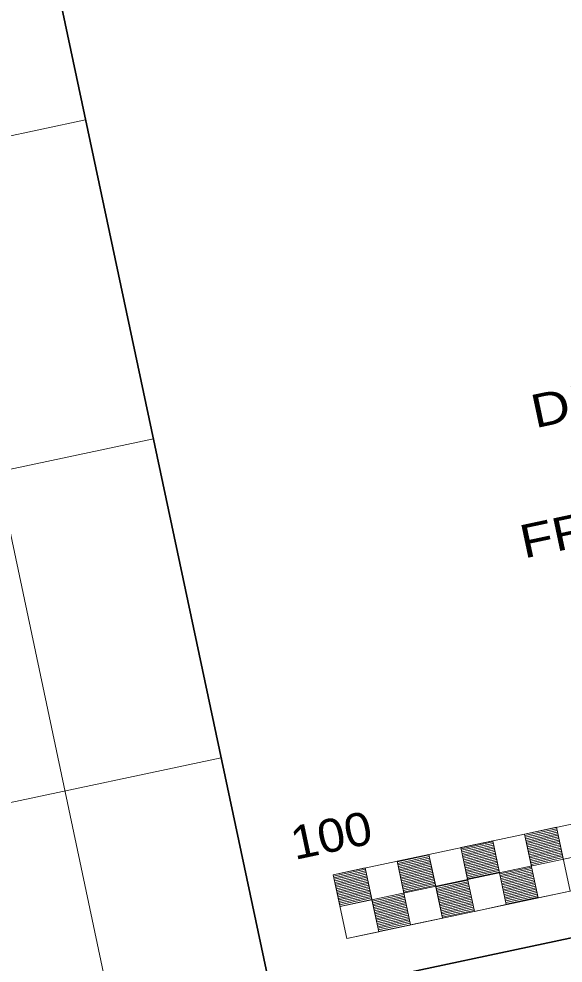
# Model space of a CAD drawing. Extents: x 2357218 to 2371708, y 6973728 to 6980157.
# Drawn here: x 2370463.2 to 2370630.2, y 6976807.8 to 6977097.4 of the extents above; entities that cross this region are included whole.
import ezdxf
from ezdxf.enums import TextEntityAlignment as Align

# ---------------------------------------------------------------- set-up
doc = ezdxf.new("R2010")
doc.units = 0
doc.header["$LTSCALE"] = 2
doc.layers.add('62', color=7, linetype='Continuous', lineweight=13)
doc.layers.add('63', color=7, linetype='Continuous', lineweight=13)

msp = doc.modelspace()

# ---------------------------------------------------------------- linework, layer by layer
at = {"layer": '62'}
for p, q in [((2370248.639, 6977936.603), (2370539.727, 6976567.134)), ((2370483.709, 6977066.421), (2358649.527, 6974550.988)), ((2370504.501, 6976968.6), (2358670.319, 6974453.169)), ((2370559.68, 6976834.897), (2370950.993, 6976918.073)), ((2370561.761, 6976825.114), (2370953.073, 6976908.29)), ((2370525.293, 6976870.783), (2358691.111, 6974355.349)), ((2370618.379, 6976847.361), (2370628.163, 6976849.442)), ((2370618.483, 6976846.872), (2370628.267, 6976848.952)), ((2370628.16, 6976849.453), (2370630.24, 6976839.67)), ((2370618.377, 6976847.373), (2370620.456, 6976837.591)), ((2370618.587, 6976846.381), (2370628.37, 6976848.462)), ((2370618.692, 6976845.892), (2370628.474, 6976847.974)), ((2370618.795, 6976845.404), (2370628.578, 6976847.483)), ((2370618.899, 6976844.915), (2370628.683, 6976846.995)), ((2370619.004, 6976844.427), (2370628.786, 6976846.505)), ((2370619.107, 6976843.937), (2370628.89, 6976846.016)), ((2370598.811, 6976843.214), (2370600.89, 6976833.431)), ((2370598.882, 6976842.88), (2370608.665, 6976844.957)), ((2370598.986, 6976842.39), (2370608.769, 6976844.469)), ((2370599.09, 6976841.9), (2370608.873, 6976843.979)), ((2370599.195, 6976841.411), (2370608.977, 6976843.489)), ((2370599.298, 6976840.921), (2370609.081, 6976843.002)), ((2370608.594, 6976845.295), (2370610.673, 6976835.511)), ((2370619.212, 6976843.448), (2370628.995, 6976845.527)), ((2370619.316, 6976842.959), (2370629.098, 6976845.038)), ((2370619.419, 6976842.469), (2370629.203, 6976844.549)), ((2370619.523, 6976841.981), (2370629.307, 6976844.059)), ((2370619.627, 6976841.491), (2370629.41, 6976843.571)), ((2370619.732, 6976841.002), (2370629.514, 6976843.082)), ((2370579.286, 6976838.872), (2370589.069, 6976840.951)), ((2370579.39, 6976838.383), (2370589.172, 6976840.462)), ((2370579.494, 6976837.892), (2370589.277, 6976839.973)), ((2370589.029, 6976841.136), (2370591.109, 6976831.353)), ((2370599.403, 6976840.433), (2370609.186, 6976842.513)), ((2370599.506, 6976839.943), (2370609.29, 6976842.023)), ((2370599.61, 6976839.454), (2370609.394, 6976841.534)), ((2370599.715, 6976838.965), (2370609.498, 6976841.045)), ((2370599.819, 6976838.476), (2370609.601, 6976840.556)), ((2370599.922, 6976837.987), (2370609.706, 6976840.067)), ((2370619.835, 6976840.513), (2370629.618, 6976842.592)), ((2370619.939, 6976840.024), (2370629.723, 6976842.104)), ((2370620.044, 6976839.535), (2370629.826, 6976841.614)), ((2370620.147, 6976839.046), (2370629.93, 6976841.125)), ((2370620.252, 6976838.557), (2370630.034, 6976840.636)), ((2370620.356, 6976838.068), (2370630.137, 6976840.147)), ((2370569.463, 6976836.975), (2370571.543, 6976827.193)), ((2370579.246, 6976839.056), (2370581.325, 6976829.274)), ((2370579.598, 6976837.404), (2370589.38, 6976839.483)), ((2370579.701, 6976836.913), (2370589.484, 6976838.995)), ((2370579.805, 6976836.425), (2370589.588, 6976838.506)), ((2370579.909, 6976835.936), (2370589.693, 6976838.016)), ((2370580.014, 6976835.447), (2370589.797, 6976837.528)), ((2370580.118, 6976834.959), (2370589.9, 6976837.037)), ((2370600.026, 6976837.498), (2370609.809, 6976839.577)), ((2370600.13, 6976837.009), (2370609.914, 6976839.088)), ((2370600.235, 6976836.52), (2370610.017, 6976838.599)), ((2370600.338, 6976836.03), (2370610.121, 6976838.11)), ((2370600.443, 6976835.542), (2370610.226, 6976837.621)), ((2370600.547, 6976835.052), (2370610.33, 6976837.132)), ((2370610.745, 6976835.176), (2370620.528, 6976837.255)), ((2370559.68, 6976834.897), (2370561.761, 6976825.114)), ((2370559.77, 6976834.475), (2370569.554, 6976836.553)), ((2370559.875, 6976833.984), (2370569.658, 6976836.064)), ((2370559.978, 6976833.495), (2370569.762, 6976835.575)), ((2370560.083, 6976833.006), (2370569.865, 6976835.085)), ((2370560.186, 6976832.517), (2370569.969, 6976834.596)), ((2370560.291, 6976832.028), (2370570.073, 6976834.107)), ((2370580.222, 6976834.47), (2370590.005, 6976836.549)), ((2370580.326, 6976833.98), (2370590.109, 6976836.06)), ((2370580.43, 6976833.492), (2370590.213, 6976835.57)), ((2370580.533, 6976833.002), (2370590.317, 6976835.081)), ((2370580.637, 6976832.514), (2370590.42, 6976834.592)), ((2370580.742, 6976832.025), (2370590.524, 6976834.103)), ((2370600.649, 6976834.564), (2370610.432, 6976836.644)), ((2370600.754, 6976834.075), (2370610.537, 6976836.153)), ((2370600.857, 6976833.586), (2370610.64, 6976835.665)), ((2370610.673, 6976835.511), (2370612.754, 6976825.728)), ((2370610.674, 6976835.512), (2370612.752, 6976825.729)), ((2370610.848, 6976834.686), (2370620.632, 6976836.766)), ((2370610.952, 6976834.198), (2370620.737, 6976836.277)), ((2370611.057, 6976833.709), (2370620.84, 6976835.788)), ((2370611.16, 6976833.219), (2370620.945, 6976835.299)), ((2370611.264, 6976832.731), (2370621.048, 6976834.808)), ((2370611.368, 6976832.241), (2370621.151, 6976834.32)), ((2370560.394, 6976831.539), (2370570.177, 6976833.618)), ((2370560.498, 6976831.05), (2370570.282, 6976833.129)), ((2370560.603, 6976830.561), (2370570.385, 6976832.64)), ((2370560.706, 6976830.071), (2370570.489, 6976832.151)), ((2370560.81, 6976829.582), (2370570.593, 6976831.662)), ((2370560.914, 6976829.093), (2370570.696, 6976831.174)), ((2370580.845, 6976831.534), (2370590.628, 6976833.614)), ((2370580.948, 6976831.046), (2370590.733, 6976833.125)), ((2370581.054, 6976830.556), (2370590.836, 6976832.636)), ((2370581.158, 6976830.067), (2370590.939, 6976832.146)), ((2370581.262, 6976829.578), (2370591.044, 6976831.658)), ((2370591.106, 6976831.352), (2370593.186, 6976821.569)), ((2370591.108, 6976831.353), (2370593.188, 6976821.569)), ((2370591.147, 6976831.169), (2370600.929, 6976833.247)), ((2370591.251, 6976830.68), (2370601.033, 6976832.758)), ((2370591.355, 6976830.19), (2370601.137, 6976832.27)), ((2370591.459, 6976829.702), (2370601.241, 6976831.78)), ((2370591.563, 6976829.212), (2370601.345, 6976831.291)), ((2370611.472, 6976831.752), (2370621.256, 6976833.831)), ((2370611.576, 6976831.263), (2370621.36, 6976833.342)), ((2370611.68, 6976830.773), (2370621.464, 6976832.853)), ((2370611.785, 6976830.285), (2370621.568, 6976832.363)), ((2370611.888, 6976829.795), (2370621.672, 6976831.876)), ((2370611.993, 6976829.306), (2370621.777, 6976831.387)), ((2370561.018, 6976828.604), (2370570.801, 6976830.685)), ((2370561.123, 6976828.115), (2370570.904, 6976830.195)), ((2370561.226, 6976827.626), (2370571.009, 6976829.707)), ((2370561.331, 6976827.137), (2370571.114, 6976829.216)), ((2370561.435, 6976826.648), (2370571.217, 6976828.728)), ((2370561.537, 6976826.16), (2370571.321, 6976828.238)), ((2370571.632, 6976826.771), (2370581.414, 6976828.85)), ((2370571.736, 6976826.282), (2370581.517, 6976828.361)), ((2370591.667, 6976828.723), (2370601.449, 6976830.802)), ((2370591.771, 6976828.235), (2370601.553, 6976830.313)), ((2370591.875, 6976827.745), (2370601.657, 6976829.824)), ((2370591.979, 6976827.256), (2370601.762, 6976829.334)), ((2370592.083, 6976826.766), (2370601.865, 6976828.847)), ((2370592.187, 6976826.277), (2370601.969, 6976828.358)), ((2370612.095, 6976828.817), (2370621.88, 6976830.898)), ((2370612.199, 6976828.327), (2370621.984, 6976830.408)), ((2370612.304, 6976827.838), (2370622.088, 6976829.917)), ((2370612.408, 6976827.349), (2370622.192, 6976829.429)), ((2370612.512, 6976826.86), (2370622.297, 6976828.94)), ((2370612.616, 6976826.37), (2370622.4, 6976828.45)), ((2370561.641, 6976825.671), (2370571.424, 6976827.75)), ((2370561.745, 6976825.181), (2370571.529, 6976827.261)), ((2370571.543, 6976827.193), (2370573.622, 6976817.41)), ((2370571.84, 6976825.793), (2370581.622, 6976827.871)), ((2370571.944, 6976825.303), (2370581.726, 6976827.383)), ((2370572.048, 6976824.814), (2370581.831, 6976826.894)), ((2370572.153, 6976824.325), (2370581.934, 6976826.404)), ((2370572.255, 6976823.836), (2370582.038, 6976825.915)), ((2370572.36, 6976823.347), (2370582.141, 6976825.425)), ((2370592.292, 6976825.788), (2370602.073, 6976827.868)), ((2370592.395, 6976825.299), (2370602.177, 6976827.379)), ((2370592.499, 6976824.81), (2370602.282, 6976826.889)), ((2370592.604, 6976824.32), (2370602.386, 6976826.4)), ((2370592.707, 6976823.832), (2370602.489, 6976825.91)), ((2370592.812, 6976823.343), (2370602.593, 6976825.422)), ((2370612.72, 6976825.881), (2370622.505, 6976827.961)), ((2370572.464, 6976822.858), (2370582.245, 6976824.937)), ((2370572.567, 6976822.369), (2370582.35, 6976824.448)), ((2370572.672, 6976821.88), (2370582.454, 6976823.958)), ((2370572.776, 6976821.39), (2370582.557, 6976823.47)), ((2370572.88, 6976820.901), (2370582.662, 6976822.98)), ((2370572.984, 6976820.411), (2370582.766, 6976822.49)), ((2370592.915, 6976822.854), (2370602.697, 6976824.933)), ((2370593.019, 6976822.365), (2370602.801, 6976824.443)), ((2370593.123, 6976821.874), (2370602.905, 6976823.955)), ((2370573.087, 6976819.922), (2370582.871, 6976822.001)), ((2370573.192, 6976819.433), (2370582.973, 6976821.511)), ((2370573.295, 6976818.943), (2370583.078, 6976821.022)), ((2370573.4, 6976818.454), (2370583.182, 6976820.534)), ((2370573.503, 6976817.965), (2370583.286, 6976820.045)), ((2370573.607, 6976817.476), (2370583.391, 6976819.556))]:
    msp.add_line(p, q, dxfattribs=at)
at = {"layer": '62', "lineweight": 35}
for p, q in [((2370463.576, 6977161.139), (2370587.67, 6976577.324)), ((2371176.22, 6976931.098), (2370539.396, 6976795.736))]:
    msp.add_line(p, q, dxfattribs=at)
at = {"layer": '62'}
for points in [[(2370622.537, 6976827.807), (2370632.319, 6976829.887), (2370628.16, 6976849.453), (2370618.377, 6976847.373)], [(2370602.971, 6976823.649), (2370612.754, 6976825.728), (2370608.594, 6976845.295), (2370598.811, 6976843.214)], [(2370583.405, 6976819.49), (2370593.188, 6976821.569), (2370589.029, 6976841.136), (2370579.246, 6976839.056)], [(2370563.839, 6976815.332), (2370573.622, 6976817.41), (2370569.463, 6976836.975), (2370559.68, 6976834.897)]]:
    msp.add_lwpolyline(points, close=True, dxfattribs=at)
at = {"layer": '63'}
for p, q in [((2370248.639, 6977936.603), (2370539.727, 6976567.134)), ((2370483.709, 6977066.421), (2358649.527, 6974550.988)), ((2370504.501, 6976968.6), (2358670.319, 6974453.169)), ((2370559.68, 6976834.897), (2370950.993, 6976918.073)), ((2370561.761, 6976825.114), (2370953.073, 6976908.29)), ((2370563.839, 6976815.332), (2370955.152, 6976898.507)), ((2370525.293, 6976870.783), (2358691.111, 6974355.349)), ((2370618.379, 6976847.361), (2370628.163, 6976849.442)), ((2370618.483, 6976846.872), (2370628.267, 6976848.952)), ((2370628.16, 6976849.453), (2370630.24, 6976839.67)), ((2370618.377, 6976847.373), (2370620.456, 6976837.591)), ((2370618.587, 6976846.381), (2370628.37, 6976848.462)), ((2370618.692, 6976845.892), (2370628.474, 6976847.974)), ((2370618.795, 6976845.404), (2370628.578, 6976847.483)), ((2370618.899, 6976844.915), (2370628.683, 6976846.995)), ((2370619.004, 6976844.427), (2370628.786, 6976846.505)), ((2370619.107, 6976843.937), (2370628.89, 6976846.016)), ((2370598.811, 6976843.214), (2370600.89, 6976833.431)), ((2370598.882, 6976842.88), (2370608.665, 6976844.957)), ((2370598.986, 6976842.39), (2370608.769, 6976844.469)), ((2370599.09, 6976841.9), (2370608.873, 6976843.979)), ((2370599.195, 6976841.411), (2370608.977, 6976843.489)), ((2370599.298, 6976840.921), (2370609.081, 6976843.002)), ((2370608.594, 6976845.295), (2370610.673, 6976835.511)), ((2370619.212, 6976843.448), (2370628.995, 6976845.527)), ((2370619.316, 6976842.959), (2370629.098, 6976845.038)), ((2370619.419, 6976842.469), (2370629.203, 6976844.549)), ((2370619.523, 6976841.981), (2370629.307, 6976844.059)), ((2370619.627, 6976841.491), (2370629.41, 6976843.571)), ((2370619.732, 6976841.002), (2370629.514, 6976843.082)), ((2370579.286, 6976838.872), (2370589.069, 6976840.951)), ((2370579.39, 6976838.383), (2370589.172, 6976840.462)), ((2370579.494, 6976837.892), (2370589.277, 6976839.973)), ((2370589.029, 6976841.136), (2370591.109, 6976831.353)), ((2370599.403, 6976840.433), (2370609.186, 6976842.513)), ((2370599.506, 6976839.943), (2370609.29, 6976842.023)), ((2370599.61, 6976839.454), (2370609.394, 6976841.534)), ((2370599.715, 6976838.965), (2370609.498, 6976841.045)), ((2370599.819, 6976838.476), (2370609.601, 6976840.556)), ((2370599.922, 6976837.987), (2370609.706, 6976840.067)), ((2370619.835, 6976840.513), (2370629.618, 6976842.592)), ((2370619.939, 6976840.024), (2370629.723, 6976842.104)), ((2370620.044, 6976839.535), (2370629.826, 6976841.614)), ((2370620.147, 6976839.046), (2370629.93, 6976841.125)), ((2370620.252, 6976838.557), (2370630.034, 6976840.636)), ((2370620.356, 6976838.068), (2370630.137, 6976840.147)), ((2370569.463, 6976836.975), (2370571.543, 6976827.193)), ((2370579.246, 6976839.056), (2370581.325, 6976829.274)), ((2370579.598, 6976837.404), (2370589.38, 6976839.483)), ((2370579.701, 6976836.913), (2370589.484, 6976838.995)), ((2370579.805, 6976836.425), (2370589.588, 6976838.506)), ((2370579.909, 6976835.936), (2370589.693, 6976838.016)), ((2370580.014, 6976835.447), (2370589.797, 6976837.528)), ((2370580.118, 6976834.959), (2370589.9, 6976837.037)), ((2370600.026, 6976837.498), (2370609.809, 6976839.577)), ((2370600.13, 6976837.009), (2370609.914, 6976839.088)), ((2370600.235, 6976836.52), (2370610.017, 6976838.599)), ((2370600.338, 6976836.03), (2370610.121, 6976838.11)), ((2370600.443, 6976835.542), (2370610.226, 6976837.621)), ((2370600.547, 6976835.052), (2370610.33, 6976837.132)), ((2370610.745, 6976835.176), (2370620.528, 6976837.255)), ((2370559.68, 6976834.897), (2370561.761, 6976825.114)), ((2370559.77, 6976834.475), (2370569.554, 6976836.553)), ((2370559.875, 6976833.984), (2370569.658, 6976836.064)), ((2370559.978, 6976833.495), (2370569.762, 6976835.575)), ((2370560.083, 6976833.006), (2370569.865, 6976835.085)), ((2370560.186, 6976832.517), (2370569.969, 6976834.596)), ((2370560.291, 6976832.028), (2370570.073, 6976834.107)), ((2370580.222, 6976834.47), (2370590.005, 6976836.549)), ((2370580.326, 6976833.98), (2370590.109, 6976836.06)), ((2370580.43, 6976833.492), (2370590.213, 6976835.57)), ((2370580.533, 6976833.002), (2370590.317, 6976835.081)), ((2370580.637, 6976832.514), (2370590.42, 6976834.592)), ((2370580.742, 6976832.025), (2370590.524, 6976834.103)), ((2370600.649, 6976834.564), (2370610.432, 6976836.644)), ((2370600.754, 6976834.075), (2370610.537, 6976836.153)), ((2370600.857, 6976833.586), (2370610.64, 6976835.665)), ((2370610.673, 6976835.511), (2370612.754, 6976825.728)), ((2370610.674, 6976835.512), (2370612.752, 6976825.729)), ((2370610.848, 6976834.686), (2370620.632, 6976836.766)), ((2370610.952, 6976834.198), (2370620.737, 6976836.277)), ((2370611.057, 6976833.709), (2370620.84, 6976835.788)), ((2370611.16, 6976833.219), (2370620.945, 6976835.299)), ((2370611.264, 6976832.731), (2370621.048, 6976834.808)), ((2370611.368, 6976832.241), (2370621.151, 6976834.32)), ((2370560.394, 6976831.539), (2370570.177, 6976833.618)), ((2370560.498, 6976831.05), (2370570.282, 6976833.129)), ((2370560.603, 6976830.561), (2370570.385, 6976832.64)), ((2370560.706, 6976830.071), (2370570.489, 6976832.151)), ((2370560.81, 6976829.582), (2370570.593, 6976831.662)), ((2370560.914, 6976829.093), (2370570.696, 6976831.174)), ((2370580.845, 6976831.534), (2370590.628, 6976833.614)), ((2370580.948, 6976831.046), (2370590.733, 6976833.125)), ((2370581.054, 6976830.556), (2370590.836, 6976832.636)), ((2370581.158, 6976830.067), (2370590.939, 6976832.146)), ((2370581.262, 6976829.578), (2370591.044, 6976831.658)), ((2370591.106, 6976831.352), (2370593.186, 6976821.569)), ((2370591.108, 6976831.353), (2370593.188, 6976821.569)), ((2370591.147, 6976831.169), (2370600.929, 6976833.247)), ((2370591.251, 6976830.68), (2370601.033, 6976832.758)), ((2370591.355, 6976830.19), (2370601.137, 6976832.27)), ((2370591.459, 6976829.702), (2370601.241, 6976831.78)), ((2370591.563, 6976829.212), (2370601.345, 6976831.291)), ((2370611.472, 6976831.752), (2370621.256, 6976833.831)), ((2370611.576, 6976831.263), (2370621.36, 6976833.342)), ((2370611.68, 6976830.773), (2370621.464, 6976832.853)), ((2370611.785, 6976830.285), (2370621.568, 6976832.363)), ((2370611.888, 6976829.795), (2370621.672, 6976831.876)), ((2370611.993, 6976829.306), (2370621.777, 6976831.387)), ((2370561.018, 6976828.604), (2370570.801, 6976830.685)), ((2370561.123, 6976828.115), (2370570.904, 6976830.195)), ((2370561.226, 6976827.626), (2370571.009, 6976829.707)), ((2370561.331, 6976827.137), (2370571.114, 6976829.216)), ((2370561.435, 6976826.648), (2370571.217, 6976828.728)), ((2370561.537, 6976826.16), (2370571.321, 6976828.238)), ((2370571.632, 6976826.771), (2370581.414, 6976828.85)), ((2370571.736, 6976826.282), (2370581.517, 6976828.361)), ((2370591.667, 6976828.723), (2370601.449, 6976830.802)), ((2370591.771, 6976828.235), (2370601.553, 6976830.313)), ((2370591.875, 6976827.745), (2370601.657, 6976829.824)), ((2370591.979, 6976827.256), (2370601.762, 6976829.334)), ((2370592.083, 6976826.766), (2370601.865, 6976828.847)), ((2370592.187, 6976826.277), (2370601.969, 6976828.358)), ((2370612.095, 6976828.817), (2370621.88, 6976830.898)), ((2370612.199, 6976828.327), (2370621.984, 6976830.408)), ((2370612.304, 6976827.838), (2370622.088, 6976829.917)), ((2370612.408, 6976827.349), (2370622.192, 6976829.429)), ((2370612.512, 6976826.86), (2370622.297, 6976828.94)), ((2370612.616, 6976826.37), (2370622.4, 6976828.45)), ((2370561.641, 6976825.671), (2370571.424, 6976827.75)), ((2370561.745, 6976825.181), (2370571.529, 6976827.261)), ((2370571.543, 6976827.193), (2370573.622, 6976817.41)), ((2370571.84, 6976825.793), (2370581.622, 6976827.871)), ((2370571.944, 6976825.303), (2370581.726, 6976827.383)), ((2370572.048, 6976824.814), (2370581.831, 6976826.894)), ((2370572.153, 6976824.325), (2370581.934, 6976826.404)), ((2370572.255, 6976823.836), (2370582.038, 6976825.915)), ((2370572.36, 6976823.347), (2370582.141, 6976825.425)), ((2370592.292, 6976825.788), (2370602.073, 6976827.868)), ((2370592.395, 6976825.299), (2370602.177, 6976827.379)), ((2370592.499, 6976824.81), (2370602.282, 6976826.889)), ((2370592.604, 6976824.32), (2370602.386, 6976826.4)), ((2370592.707, 6976823.832), (2370602.489, 6976825.91)), ((2370592.812, 6976823.343), (2370602.593, 6976825.422)), ((2370612.72, 6976825.881), (2370622.505, 6976827.961)), ((2370572.464, 6976822.858), (2370582.245, 6976824.937)), ((2370572.567, 6976822.369), (2370582.35, 6976824.448)), ((2370572.672, 6976821.88), (2370582.454, 6976823.958)), ((2370572.776, 6976821.39), (2370582.557, 6976823.47)), ((2370572.88, 6976820.901), (2370582.662, 6976822.98)), ((2370572.984, 6976820.411), (2370582.766, 6976822.49)), ((2370592.915, 6976822.854), (2370602.697, 6976824.933)), ((2370593.019, 6976822.365), (2370602.801, 6976824.443)), ((2370593.123, 6976821.874), (2370602.905, 6976823.955)), ((2370573.087, 6976819.922), (2370582.871, 6976822.001)), ((2370573.192, 6976819.433), (2370582.973, 6976821.511)), ((2370573.295, 6976818.943), (2370583.078, 6976821.022)), ((2370573.4, 6976818.454), (2370583.182, 6976820.534)), ((2370573.503, 6976817.965), (2370583.286, 6976820.045)), ((2370573.607, 6976817.476), (2370583.391, 6976819.556))]:
    msp.add_line(p, q, dxfattribs=at)
at = {"layer": '63', "lineweight": 35}
msp.add_line((2370463.576, 6977161.139), (2370587.67, 6976577.324), dxfattribs=at)
at = {"layer": '63'}
for points in [[(2370622.537, 6976827.807), (2370632.319, 6976829.887), (2370628.16, 6976849.453), (2370618.377, 6976847.373)], [(2370602.971, 6976823.649), (2370612.754, 6976825.728), (2370608.594, 6976845.295), (2370598.811, 6976843.214)], [(2370583.405, 6976819.49), (2370593.188, 6976821.569), (2370589.029, 6976841.136), (2370579.246, 6976839.056)], [(2370563.839, 6976815.332), (2370573.622, 6976817.41), (2370569.463, 6976836.975), (2370559.68, 6976834.897)]]:
    msp.add_lwpolyline(points, close=True, dxfattribs=at)

# ---------------------------------------------------------------- texts
at = {"layer": '62'}
for s, width, p in [('DIRECT CONNECTOR & RAMP DESIGN SPEED = 50 MPH', 1.2, (2370838.46, 6977017.911)), ('FRONTAGE ROAD DESIGN SPEED VARIABLE 35 TO 40 MPH', 1.2, (2370847.295, 6976980.56)), ('100', 1.1, (2370560.11, 6976841.999))]:
    msp.add_text(s, height=10.2, rotation=12, dxfattribs=dict(at, width=width)).set_placement(p, align=Align.CENTER)
at = {"layer": '63'}
for s, width, p in [('DIRECT CONNECTOR & RAMP DESIGN SPEED = 50 MPH', 1.2, (2370838.46, 6977017.911)), ('100', 1.1, (2370560.11, 6976841.999))]:
    msp.add_text(s, height=10.2, rotation=12, dxfattribs=dict(at, width=width)).set_placement(p, align=Align.CENTER)

doc.saveas('drawing.dxf')
